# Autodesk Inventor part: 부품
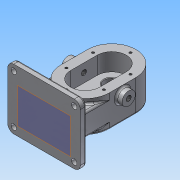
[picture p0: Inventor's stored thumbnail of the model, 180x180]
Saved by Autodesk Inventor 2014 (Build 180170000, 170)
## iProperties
Created: 2020-09
Part Number: 부품
Material: 알루미늄 6061
Document SubType Name: Modeling
Designer: NET
Density: 2.71 g/cm^3
Appearance: 알루미늄 - 평지
Mass: 1445.79 g
Surface Area: 785.826 cm^2
Volume: 533.501 cm^3
Author: NET
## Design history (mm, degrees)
sketch "스케치1"
  geometry: L1 (0, 22)-(0, -22); L2 (-40, 22)-(-40, -22); L3 (40, -22)-(40, 22); A1 r 40 centre (0, 22) between (40, 22) and (-40, 22); A2 r 40 centre (0, -22) between (-40, -22) and (40, -22); 3 further points
  constraints: 8 end point, 4 point on circle, 4 tangent, 2 centre point, 2 midpoint, 1 coincident, 1 horizontal alignment, 1 parallel, 1 vertical
  dimensions: "d4" = 44 distance of L3.start L3.end; "d5" = 40 radius of A1
extrude "돌출1" new body sketch "스케치1" distance "d6" = 53; taper "d7" = 0 deg
sketch "스케치2"
  geometry: L1 (-40, 22)-(-40, -22) reference; L2 (0, 22)-(0, -22); L3 (-24, 22)-(-24, -22); L4 (24, -22)-(24, 22); A1 r 24 centre (0, 22) between (24, 22) and (-24, 22); A2 r 24 centre (0, -22) between (-24, -22) and (24, -22); 2 further points
  constraints: 8 end point, 4 point on circle, 4 tangent, 2 centre point, 2 coincident, 2 parallel, 1 midpoint
  dimensions: "d8" = 24 radius of A1; "d9" = 44 distance of L4.start L4.end
extrude "돌출2" cut sketch "스케치2" distance "d10" = 29; taper "d11" = 0 deg
node "작업 평면1"
sketch "스케치3"
  geometry: C1 r 12.5 at (0, 22); C2 r 12.5 at (0, -22); A1 r 24 centre (0, -22) between (-24, -22) and (24, -22) reference; A2 r 24 centre (0, 22) between (24, 22) and (-24, 22) reference; 1 further point
  constraints: 2 centre point, 2 coincident
  dimensions: "d13" = 25 diameter of C1; "d14" = 25 diameter of C2
extrude "돌출3" cut sketch "스케치3" distance "d15" = 15; taper "d16" = 0 deg
sketch "스케치4"
  geometry: C1 r 12.5 at (0, 0) reference; C2 r 8.5 at (0, 0); 1 further point
  constraints: 1 centre point, 1 coincident
  dimensions: "d17" = 17 diameter of C2
extrude "돌출4" cut sketch "스케치4" stored distance "d18" = 15; taper "d19" = 0 deg
sketch "스케치5"
  geometry: C1 r 8.5 at (0, 22) reference; C2 r 19 at (0, 22); A1 r 40 centre (0, 22) between (40, 22) and (-40, 22) reference; 1 further point
  constraints: 1 centre point, 1 coincident
  dimensions: "d20" = 38 diameter of C2
extrude "돌출5" join sketch "스케치5" distance "d21" = 17; taper "d22" = 0 deg
sketch "스케치6"
  geometry: C1 r 8.5 at (0, 0) reference; C2 r 19 at (0, 0) reference; C3 r 14 at (0, 0); 1 further point
  constraints: 1 centre point, 1 coincident
  dimensions: "d23" = 28 diameter of C3
extrude "돌출6" cut sketch "스케치6" distance "d24" = 7.3; taper "d25" = 0 deg
sketch "스케치7"
  geometry: L1 (-19, -17)-(19, -17) reference; L2 (-60, 83)-(60, 83); L3 (60, 83)-(60, -17); L4 (60, -17)-(-60, -17); L5 (-60, -17)-(-60, 83); 2 further points
  constraints: 8 end point, 3 parallel, 2 midpoint, 1 perpendicular
  dimensions: "d26" = 100 distance of L2.end L3.end; "d27" = 120 distance of L3.end L4.end
extrude "돌출7" join sketch "스케치7" distance "d28" = 10; taper "d29" = 0 deg
sketch "스케치8"
  geometry: L1 (60, 17)-(-60, 17) reference; L2 (-40, -45)-(40, -45); L3 (40, -45)-(40, -8); L4 (40, -8)-(-40, -8); L5 (-40, -45)-(-40, -8); 2 further points
  constraints: 8 end point, 2 vertical, 1 horizontal, 1 midpoint, 1 perpendicular, 1 vertical alignment
  dimensions: "d30" = 80 distance of L2.start L2.end; "d31" = 37 distance of L2.end L3.end; "d32" = 25 distance between parallel lines of L1 L4
extrude "돌출8" join sketch "스케치8" stored distance "d33" = 10; taper "d34" = 0 deg
node "작업 평면2"
sketch "스케치9"
  geometry: L1 (-90, 83)-(-90, -17) reference; L2 (-22, 53)-(22, 53) reference; C1 r 11 at (0, 39); 2 further points
  constraints: 1 centre point, 1 midpoint, 1 vertical alignment
  dimensions: "d36" = 22 diameter of C1; "d72" = 14 distance from line of L2 C1.centre
extrude "돌출9" join sketch "스케치9" stored distance "d37" = 10; taper "d38" = 0 deg
sketch "스케치10"
  geometry: C1 r 11 at (0, 0) reference; 2 further points
  constraints: 1 coincident
hole "구멍1" sketch "스케치10" at (0, 0) diameter "d39" = 8.376; stored, may be unused: countersink angle "d43" = 90 deg, drill point angle "d45" = 118 deg; dims "d40" = 6, "d41" = 4, "d42" = 2, "d44" = 8
sketch "스케치11"
  geometry: A1 r 24 centre (0, -22) between (-24, -22) and (24, -22) reference; A2 r 24 centre (0, 22) between (24, 22) and (-24, 22) reference; 7 further points
  constraints: 4 horizontal alignment, 4 vertical alignment
  dimensions: "d46" = 31 distance of A1.centre point (-31, -22); "d47" = 31 distance of point (31, 22) A2.centre; "d48" = 31 distance of point (0, 53) A2.centre; "d49" = 31 distance of point (0, -53) A1.centre
hole "구멍2" sketch "스케치11" at (0, 53), (31, 22), (-31, 22), (-31, -22), (31, -22), (0, -53) diameter "d50" = 4.134; stored, may be unused: countersink angle "d54" = 90 deg, drill point angle "d56" = 118 deg; dims "d51" = 10, "d52" = 4, "d53" = 2, "d55" = 12
chamfer "모따기1" distance "d57" = 0.7; stored, may be unused: second distance "d58" = 2, angle "d59" = 30 deg
chamfer "모따기2" distance "d60" = 1; stored, may be unused: second distance "d61" = 2, angle "d62" = 30 deg
sketch "스케치12"
  geometry: L1 (-60, -83)-(60, -83) reference; L2 (60, -83)-(60, 17) reference; L3 (60, 17)-(-60, 17) reference; L4 (-60, 17)-(-60, -83) reference; C1 r 4.5 at (-50, 7); C2 r 4.5 at (50, 7); C3 r 4.5 at (50, -73); C4 r 4.5 at (-50, -73); 1 further point
  constraints: 4 centre point, 3 equal radius, 2 horizontal alignment, 2 vertical alignment
  dimensions: "d63" = 9 diameter of C1; "d64" = 10 distance from line of L3 C1.centre; "d65" = 10 distance from line of L4 C1.centre; "d66" = 10 distance from line of L2 C2.centre; "d67" = 10 distance from line of L1 C4.centre
extrude "돌출10" cut sketch "스케치12" distance "d68" = 10; taper "d69" = 0 deg
fillet "모깎기1" dims "d70" = 3
fillet "모깎기2" dims "d71" = 3
fillet "모깎기3" dims "d73" = 10
fillet "모깎기4" dims "d74" = 3
fillet "모깎기5" dims "d75" = 3
sketch "스케치13"
  geometry: L1 (-50, -83)-(50, -83) reference; L2 (-60, 7)-(-60, -73) reference; 2 further points
  constraints: 1 other
  dimensions: "d76" = 12 distance from line of L1 point (0, -71); "d77" = 60 distance from line of point (0, -71) L2
feature "엠보싱1" sketch "스케치13" dims "d4" = 44, "d5" = 40, "d78" = 0.5, "d79" = 0
fillet "모깎기6" dims "d80" = 0.5
node "솔리드1"
mirror "대칭1"
